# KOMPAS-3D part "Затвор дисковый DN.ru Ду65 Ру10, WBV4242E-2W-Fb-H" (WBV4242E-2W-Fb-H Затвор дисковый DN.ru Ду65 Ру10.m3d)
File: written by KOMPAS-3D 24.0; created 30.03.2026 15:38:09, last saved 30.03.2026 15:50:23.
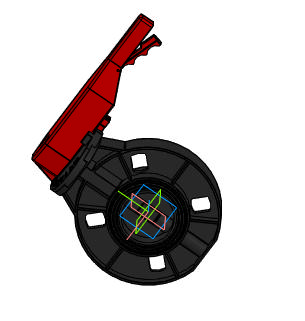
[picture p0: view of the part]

Document properties: Автор: R2D2; Полное имя файла: E:\Работа\Зайцев\WBV4242E-2W-Fb-H Затвор дисковый DN.ru Ду50-200 Ру10\DN65\WBV4242E-2W-Fb-H Затвор дисковый DN.ru Ду65 Ру10.m3d

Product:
- Part/product: Затвор дисковый DN.ru Ду65 Ру10  | designation WBV4242E-2W-Fb-H
    Масса: 1.31
    Раздел спецификации: Прочие изделия
    Примечание: D050-81198

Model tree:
1. Операция без истории:2

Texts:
  WBV4242E-2W-Fb-H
